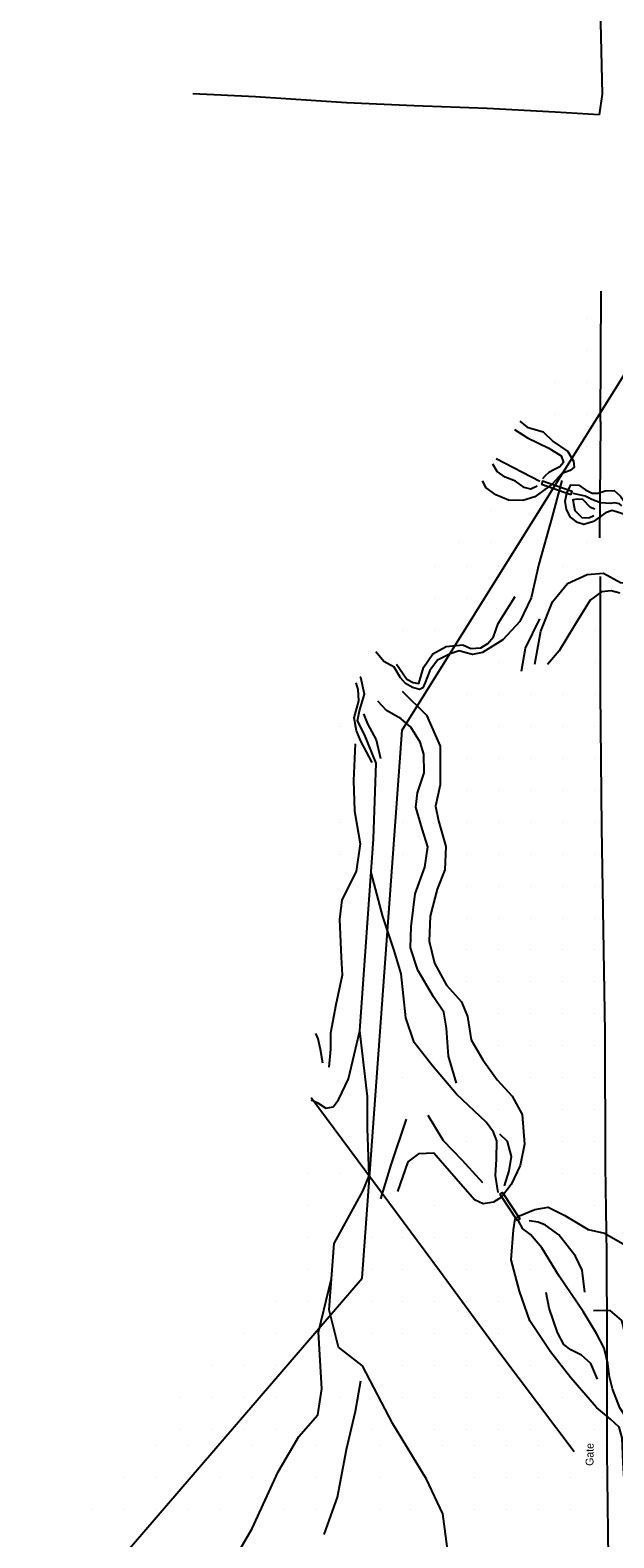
# Model space of a CAD drawing. Extents: x 19528164 to 19545171, y 7585743 to 7602745.
# Drawn here: x 19541417 to 19541782, y 7597047 to 7597991 of the extents above; entities that cross this region are included whole.
import ezdxf

# ---------------------------------------------------------------- set-up
doc = ezdxf.new("R2010")
doc.units = 0
for name, color, linetype in [('PhoBreakLine', 7, 'Continuous'), ('PhoCulvert', 7, 'Continuous'), ('PhoDrainageArrow', 7, 'Continuous'), ('PhoFence', 7, 'Continuous'), ('PhoISAEPoints', 7, 'Continuous'), ('PhoNotesDesign', 7, 'Continuous'), ('PhoSurveyLimits', 7, 'Continuous'), ('SurBreakLine', 7, 'Continuous'), ('SurEdgeEntranceUnpaved', 7, 'Continuous')]:
    doc.layers.add(name, color=color, linetype=linetype)

msp = doc.modelspace()

# ---------------------------------------------------------------- linework, layer by layer
at = {"layer": 'PhoBreakLine'}
for points in [[(19541723.1, 7597745.86), (19541727.72, 7597742.14), (19541737.65, 7597739.17), (19541744.06, 7597733.16), (19541753.15, 7597726.84), (19541756.71, 7597720.88), (19541757.17, 7597717.01), (19541754.71, 7597714.93), (19541749.52, 7597713.12), (19541743.3, 7597706.43), (19541732.59, 7597698.53), (19541724.92, 7597696.19), (19541716.1, 7597696.55), (19541708.08, 7597699.87), (19541702.1, 7597704.14), (19541699.82, 7597708.59)], [(19541719.9, 7597740.74), (19541727.87, 7597735.55), (19541741.23, 7597729.07), (19541748.96, 7597724.11), (19541750.44, 7597720.12), (19541748.08, 7597717.24), (19541744.37, 7597715.44), (19541741.19, 7597713.71), (19541739.03, 7597711.63), (19541737.32, 7597709.82)], [(19541733.96, 7597705.23), (19541730.07, 7597703.39), (19541725.87, 7597704.4), (19541720.42, 7597708.37), (19541713.98, 7597710.82), (19541708.94, 7597714.39), (19541706.25, 7597718.89)], [(19541749.32, 7597708.66), (19541743.07, 7597685.46), (19541734.99, 7597656.4), (19541730.3, 7597635.35), (19541723.22, 7597620.51), (19541712.57, 7597608.96), (19541699.77, 7597601.11), (19541693.51, 7597599.91), (19541688.72, 7597601.08), (19541685.1, 7597602.23), (19541679.56, 7597600.28), (19541671.6, 7597596.34), (19541666.84, 7597589.94), (19541663.88, 7597582.29), (19541662.37, 7597579.1), (19541660.29, 7597578), (19541655.91, 7597579.32), (19541651.51, 7597581.84), (19541648.43, 7597585.27), (19541644.46, 7597592.02), (19541638.04, 7597595.49), (19541632.9, 7597601.51)], [(19541790.02, 7597687.08), (19541780.99, 7597689.93), (19541776.86, 7597688.62), (19541769.15, 7597683.21), (19541763.12, 7597681.25), (19541759.23, 7597682.58), (19541754.77, 7597685.81), (19541752.34, 7597690.71), (19541751.47, 7597695.78), (19541752.59, 7597700.91), (19541755.01, 7597706.11), (19541760, 7597705.74), (19541764.14, 7597703), (19541768.36, 7597700.74), (19541772.19, 7597700.8), (19541776.62, 7597702.38), (19541782.18, 7597702.46), (19541786.15, 7597698.87), (19541789.93, 7597693.58), (19541789.8, 7597690.06)], [(19541770.15, 7597690.88), (19541767.29, 7597691.78), (19541762.58, 7597696.96), (19541759.37, 7597697.05), (19541756.31, 7597696.69), (19541757.65, 7597690.08), (19541761.99, 7597685.6), (19541766.4, 7597685.31), (19541769.36, 7597686.91)], [(19541732.47, 7597593.93), (19541736.31, 7597614.51), (19541743.61, 7597632.88), (19541753.02, 7597644.28), (19541765.27, 7597649.93), (19541775.46, 7597650.8), (19541786.14, 7597644.85), (19541799.39, 7597643.17), (19541811.74, 7597638.99), (19541823.27, 7597630.34), (19541832.56, 7597627.85), (19541841.75, 7597627.23)], [(19541645.9, 7597593.78), (19541652.41, 7597584.39), (19541656.4, 7597582.36), (19541659.88, 7597581.69), (19541662.76, 7597591.84), (19541668.61, 7597600.3), (19541677.09, 7597604.83), (19541687.54, 7597605.97), (19541692.43, 7597603.54), (19541698.74, 7597604.04), (19541703.11, 7597606.73), (19541706.66, 7597610.92), (19541709.52, 7597619.33), (19541720.14, 7597636.27)], [(19541785.75, 7597638.25), (19541780.28, 7597639.67), (19541774.31, 7597639.15), (19541767.22, 7597633.82), (19541757.4, 7597618.05), (19541747.81, 7597602.11), (19541740.55, 7597593.55)], [(19541724.27, 7597589.51), (19541726.59, 7597603.93), (19541735.75, 7597622.3)], [(19541630.8, 7597532.29), (19541623.52, 7597545.63), (19541620.98, 7597552.18), (19541619.34, 7597560.31), (19541622.31, 7597570.82), (19541621.98, 7597577.89), (19541620.75, 7597582.07)], [(19541649.49, 7597576.87), (19541664.76, 7597561.95), (19541673.37, 7597542.44), (19541673.23, 7597518.3), (19541670.31, 7597504.94), (19541672.27, 7597495.8), (19541676.78, 7597479.66), (19541676.1, 7597465.22), (19541671.38, 7597453.04), (19541666.95, 7597436.05), (19541666.33, 7597420.41), (19541669.65, 7597406.75), (19541677.15, 7597392.96), (19541686.7, 7597382.64), (19541690.35, 7597373.43), (19541692.7, 7597358.77), (19541699.96, 7597346.36), (19541708.92, 7597333.71), (19541718.37, 7597323.52), (19541724.59, 7597312.08), (19541726.11, 7597293.4), (19541723.37, 7597280.04), (19541717.66, 7597268.2), (19541711.72, 7597260.37), (19541706.74, 7597257.14), (19541700.25, 7597256.24), (19541694.78, 7597258.61), (19541683.28, 7597271.84), (19541669.33, 7597287.76), (19541659.63, 7597287.49), (19541652.98, 7597282.36), (19541646.52, 7597263.92)], [(19541683.46, 7597331.61), (19541678.4, 7597348.59), (19541677.17, 7597366.16), (19541675.6, 7597375.98), (19541669.18, 7597385.63), (19541659.23, 7597402.28), (19541654.8, 7597416.28), (19541655.09, 7597429.65), (19541657.64, 7597450.12), (19541663.72, 7597466.87), (19541665.54, 7597479.45), (19541661.95, 7597490.75), (19541657.97, 7597504.36), (19541659.08, 7597513.38), (19541663.22, 7597525.9), (19541663.09, 7597537.52), (19541660.71, 7597545.06), (19541654.88, 7597554.46), (19541648.83, 7597559.71), (19541639.76, 7597564.84), (19541634.29, 7597570.59)], [(19541625.32, 7597562.85), (19541627.73, 7597556.51), (19541633.3, 7597546.57), (19541635.84, 7597534.77)], [(19541620.16, 7597544.02), (19541619.11, 7597521.1), (19541619.69, 7597502), (19541623.24, 7597481.34), (19541620.64, 7597464.12), (19541611.81, 7597446.31), (19541610.26, 7597434.04), (19541611.22, 7597410.41), (19541611.83, 7597399.29), (19541607.87, 7597380.71), (19541604.61, 7597362.98), (19541604.58, 7597353.01), (19541603.54, 7597341.77)], [(19541599.86, 7597344.08), (19541598.44, 7597352.78), (19541596.96, 7597359.44), (19541595.47, 7597362.68)], [(19541699.91, 7597269.24), (19541687.05, 7597283.57), (19541675.3, 7597295.64), (19541665.85, 7597311.44)], [(19541636.04, 7597259.27), (19541642.59, 7597280.56), (19541652.14, 7597309.11)], [(19541713.45, 7597267.34), (19541716.38, 7597276.88), (19541717.87, 7597285.79), (19541715.41, 7597295.16), (19541710.62, 7597299.65)], [(19541795.75, 7596912.33), (19541789.01, 7596945.85), (19541786.33, 7596982.08), (19541788.28, 7597023.7), (19541789.72, 7597063.68), (19541787.78, 7597094.06), (19541787.29, 7597109.81), (19541785.25, 7597116.43), (19541779.94, 7597121.37), (19541771.08, 7597128.81), (19541755.05, 7597147.28), (19541742.23, 7597163.64), (19541729.45, 7597183), (19541722.84, 7597201.43), (19541717.71, 7597221.16), (19541719.24, 7597239.84), (19541720.2, 7597246.68), (19541723.03, 7597248.61), (19541732.61, 7597252.67), (19541740.78, 7597254.06), (19541751.28, 7597248.94), (19541765.98, 7597240.04), (19541776.09, 7597237.72), (19541791.71, 7597228.84)], [(19541763.85, 7597200.84), (19541762.23, 7597214.58), (19541757.9, 7597223.32), (19541747.61, 7597236.85), (19541739.16, 7597242.79), (19541734.62, 7597244.67), (19541728.94, 7597245.47)], [(19541771.76, 7597146.39), (19541767.59, 7597156.19), (19541761.81, 7597161.42), (19541755.12, 7597164.78), (19541750.74, 7597168.12), (19541746.69, 7597175.54), (19541741.51, 7597190.82), (19541739.55, 7597200.57)], [(19541797.71, 7597110.7), (19541802.13, 7597125.51), (19541799.15, 7597140.88), (19541792.02, 7597162), (19541786.98, 7597183.11), (19541779.58, 7597189.35), (19541769.34, 7597189.29)], [(19541600.59, 7597049.3), (19541609.04, 7597072.62), (19541614.71, 7597102.33), (19541620.31, 7597126.34), (19541623.69, 7597145.3)]]:
    msp.add_lwpolyline(points, dxfattribs=at)
at = {"layer": 'PhoCulvert'}
for p, q in [((19541755.09, 7597699.74), (19541736.64, 7597706.21)), ((19541710.68, 7597262.25), (19541721.44, 7597245.73))]:
    msp.add_line(p, q, dxfattribs=at)
for points in [[(19541755.09, 7597699.74), (19541755.85, 7597701.92), (19541737.4, 7597708.39), (19541736.64, 7597706.21)], [(19541710.68, 7597262.25), (19541712.31, 7597263.31), (19541723.07, 7597246.79), (19541721.44, 7597245.73)]]:
    msp.add_lwpolyline(points, dxfattribs=at)
at = {"layer": 'PhoDrainageArrow'}
msp.add_line((19541735.69, 7597708.23), (19541708.38, 7597722.29), dxfattribs=at)
for points in [[(19541786.97, 7597692.87), (19541785.45, 7597694.17), (19541782.36, 7597694.7), (19541780.12, 7597694.27), (19541773.6, 7597694.7), (19541768.16, 7597696.82), (19541764.12, 7597699.05), (19541756.53, 7597700.66)], [(19541678.14, 7597038.63), (19541674.89, 7597062.11), (19541664.66, 7597083.83), (19541643.65, 7597118.47), (19541624.75, 7597154.78), (19541609.65, 7597166.56), (19541603.77, 7597189.89), (19541606.98, 7597231.3), (19541624.9, 7597263.99), (19541628.93, 7597273.62), (19541627.8, 7597303.41), (19541627.72, 7597323.36), (19541623.05, 7597364.33), (19541631.46, 7597484.45), (19541633.28, 7597531.8), (19541626.01, 7597549.86), (19541621.56, 7597558.46), (19541622.83, 7597564.55), (19541625.94, 7597575.08), (19541623.58, 7597585.48), (19541623.19, 7597585.96)], [(19541709.67, 7597263.17), (19541707.99, 7597273.84), (19541708.48, 7597284.08), (19541708.73, 7597295.67), (19541706.74, 7597301.03), (19541701.98, 7597307.25), (19541683.48, 7597324.8), (19541668.45, 7597342.58), (19541657.07, 7597357.15), (19541651.88, 7597372.44), (19541648.93, 7597400.02), (19541644.52, 7597414.6), (19541637.42, 7597435.85), (19541629.99, 7597463.4)], [(19541592.45, 7597321.29), (19541596.22, 7597319.54), (19541601.7, 7597316.02), (19541606.23, 7597316.85), (19541609.73, 7597321.23), (19541615.87, 7597334.39), (19541623.05, 7597364.33)], [(19541869.28, 7596982.98), (19541854.16, 7597003.81), (19541844.16, 7597016.82), (19541839.53, 7597029.11), (19541837.27, 7597044.4), (19541831.15, 7597053.31), (19541820.27, 7597065.93), (19541805.81, 7597091.14), (19541797.08, 7597101.96), (19541793.45, 7597109.51), (19541792.72, 7597116.12), (19541790.48, 7597121.1), (19541785.79, 7597128.46), (19541781.24, 7597140.49), (19541779.22, 7597147.88), (19541778.25, 7597156.19), (19541775.82, 7597165.87), (19541771.19, 7597174.93), (19541762.79, 7597188.82), (19541747.75, 7597210.8), (19541737, 7597228.64), (19541729.79, 7597237.06), (19541725.03, 7597240.56), (19541722.24, 7597245.49)], [(19541418.25, 7596875.86), (19541452.62, 7596909.19), (19541485.87, 7596946.26), (19541511.57, 7596977.54), (19541535.3, 7597018.21), (19541555.62, 7597053), (19541571.97, 7597088.43), (19541584.71, 7597110.46), (19541596.64, 7597124.12), (19541599.2, 7597140.35), (19541597.16, 7597175.77), (19541605.29, 7597209.5)]]:
    msp.add_lwpolyline(points, dxfattribs=at)
at = {"layer": 'PhoFence'}
for q in [(19541774.01, 7597827.32), (19541773.04, 7597672.87)]:
    msp.add_line((19541773.57, 7597745.59), q, dxfattribs=at)
for points in [[(19541777.72, 7597100.95), (19541777.8, 7597171.2), (19541777.66, 7597224.89), (19541776.78, 7597279.98), (19541776.55, 7597363.47), (19541774.39, 7597491.54), (19541773.67, 7597576.04), (19541773.63, 7597648.62)], [(19541757.22, 7597100.96), (19541711.25, 7597161.92), (19541672.75, 7597214.17), (19541645.99, 7597250.58), (19541592.54, 7597322.44)], [(19541781.43, 7596887.24), (19541779.78, 7596935.19), (19541778.75, 7597017.64), (19541777.72, 7597100.95)]]:
    msp.add_lwpolyline(points, dxfattribs=at)
at = {"layer": 'PhoISAEPoints'}
for p, q in [((19541765, 7597810), (19541765, 7597810)), ((19541765, 7597790), (19541765, 7597790)), ((19541745, 7597770), (19541745, 7597770)), ((19541765, 7597770), (19541765, 7597770)), ((19541745, 7597750), (19541745, 7597750)), ((19541765, 7597750), (19541765, 7597750)), ((19541765, 7597730), (19541765, 7597730)), ((19541705, 7597690), (19541705, 7597690)), ((19541685, 7597670), (19541685, 7597670)), ((19541705, 7597670), (19541705, 7597670)), ((19541725, 7597670), (19541725, 7597670)), ((19541765, 7597670), (19541765, 7597670)), ((19541670, 7597655), (19541670, 7597655)), ((19541690, 7597655), (19541690, 7597655)), ((19541710, 7597655), (19541710, 7597655)), ((19541750, 7597655), (19541750, 7597655)), ((19541670, 7597635), (19541670, 7597635)), ((19541690, 7597635), (19541690, 7597635)), ((19541650, 7597615), (19541650, 7597615)), ((19541670, 7597615), (19541670, 7597615)), ((19541770, 7597615), (19541770, 7597615)), ((19541710, 7597595), (19541710, 7597595)), ((19541770, 7597595), (19541770, 7597595)), ((19541690, 7597575), (19541690, 7597575)), ((19541710, 7597575), (19541710, 7597575)), ((19541730, 7597575), (19541730, 7597575)), ((19541750, 7597575), (19541750, 7597575)), ((19541770, 7597575), (19541770, 7597575)), ((19541610, 7597555), (19541610, 7597555)), ((19541690, 7597555), (19541690, 7597555)), ((19541710, 7597555), (19541710, 7597555)), ((19541730, 7597555), (19541730, 7597555)), ((19541750, 7597555), (19541750, 7597555)), ((19541770, 7597555), (19541770, 7597555)), ((19541650, 7597535), (19541650, 7597535)), ((19541690, 7597535), (19541690, 7597535)), ((19541710, 7597535), (19541710, 7597535)), ((19541730, 7597535), (19541730, 7597535)), ((19541750, 7597535), (19541750, 7597535)), ((19541770, 7597535), (19541770, 7597535)), ((19541690, 7597515), (19541690, 7597515)), ((19541710, 7597515), (19541710, 7597515)), ((19541730, 7597515), (19541730, 7597515)), ((19541750, 7597515), (19541750, 7597515)), ((19541770, 7597515), (19541770, 7597515)), ((19541610, 7597495), (19541610, 7597495)), ((19541650, 7597495), (19541650, 7597495)), ((19541690, 7597495), (19541690, 7597495)), ((19541710, 7597495), (19541710, 7597495)), ((19541730, 7597495), (19541730, 7597495)), ((19541750, 7597495), (19541750, 7597495)), ((19541770, 7597495), (19541770, 7597495)), ((19541610, 7597475), (19541610, 7597475)), ((19541650, 7597475), (19541650, 7597475)), ((19541690, 7597475), (19541690, 7597475)), ((19541710, 7597475), (19541710, 7597475)), ((19541730, 7597475), (19541730, 7597475)), ((19541750, 7597475), (19541750, 7597475)), ((19541770, 7597475), (19541770, 7597475)), ((19541690, 7597455), (19541690, 7597455)), ((19541710, 7597455), (19541710, 7597455)), ((19541730, 7597455), (19541730, 7597455)), ((19541750, 7597455), (19541750, 7597455)), ((19541770, 7597455), (19541770, 7597455)), ((19541690, 7597435), (19541690, 7597435)), ((19541710, 7597435), (19541710, 7597435)), ((19541730, 7597435), (19541730, 7597435)), ((19541750, 7597435), (19541750, 7597435)), ((19541770, 7597435), (19541770, 7597435)), ((19541690, 7597415), (19541690, 7597415)), ((19541710, 7597415), (19541710, 7597415)), ((19541730, 7597415), (19541730, 7597415)), ((19541750, 7597415), (19541750, 7597415)), ((19541770, 7597415), (19541770, 7597415)), ((19541690, 7597395), (19541690, 7597395)), ((19541710, 7597395), (19541710, 7597395)), ((19541730, 7597395), (19541730, 7597395)), ((19541750, 7597395), (19541750, 7597395)), ((19541770, 7597395), (19541770, 7597395)), ((19541710, 7597375), (19541710, 7597375)), ((19541730, 7597375), (19541730, 7597375)), ((19541750, 7597375), (19541750, 7597375)), ((19541770, 7597375), (19541770, 7597375)), ((19541710, 7597355), (19541710, 7597355)), ((19541730, 7597355), (19541730, 7597355)), ((19541750, 7597355), (19541750, 7597355)), ((19541770, 7597355), (19541770, 7597355)), ((19541650, 7597335), (19541650, 7597335)), ((19541730, 7597335), (19541730, 7597335)), ((19541750, 7597335), (19541750, 7597335)), ((19541770, 7597335), (19541770, 7597335)), ((19541710, 7597315), (19541710, 7597315)), ((19541750, 7597315), (19541750, 7597315)), ((19541770, 7597315), (19541770, 7597315)), ((19541610, 7597295), (19541610, 7597295)), ((19541690, 7597295), (19541690, 7597295)), ((19541750, 7597295), (19541750, 7597295)), ((19541770, 7597295), (19541770, 7597295)), ((19541590, 7597275), (19541590, 7597275)), ((19541610, 7597275), (19541610, 7597275)), ((19541750, 7597275), (19541750, 7597275)), ((19541770, 7597275), (19541770, 7597275)), ((19541590, 7597255), (19541590, 7597255)), ((19541670, 7597255), (19541670, 7597255)), ((19541770, 7597255), (19541770, 7597255)), ((19541590, 7597235), (19541590, 7597235)), ((19541630, 7597235), (19541630, 7597235)), ((19541650, 7597235), (19541650, 7597235)), ((19541670, 7597235), (19541670, 7597235)), ((19541690, 7597235), (19541690, 7597235)), ((19541590, 7597215), (19541590, 7597215)), ((19541630, 7597215), (19541630, 7597215)), ((19541650, 7597215), (19541650, 7597215)), ((19541670, 7597215), (19541670, 7597215)), ((19541690, 7597215), (19541690, 7597215)), ((19541730, 7597215), (19541730, 7597215)), ((19541570, 7597195), (19541570, 7597195)), ((19541590, 7597195), (19541590, 7597195)), ((19541630, 7597195), (19541630, 7597195)), ((19541650, 7597195), (19541650, 7597195)), ((19541670, 7597195), (19541670, 7597195)), ((19541690, 7597195), (19541690, 7597195)), ((19541710, 7597195), (19541710, 7597195)), ((19541550, 7597175), (19541550, 7597175)), ((19541570, 7597175), (19541570, 7597175)), ((19541630, 7597175), (19541630, 7597175)), ((19541650, 7597175), (19541650, 7597175)), ((19541670, 7597175), (19541670, 7597175)), ((19541690, 7597175), (19541690, 7597175)), ((19541710, 7597175), (19541710, 7597175)), ((19541530, 7597155), (19541530, 7597155)), ((19541550, 7597155), (19541550, 7597155)), ((19541570, 7597155), (19541570, 7597155)), ((19541650, 7597155), (19541650, 7597155)), ((19541670, 7597155), (19541670, 7597155)), ((19541690, 7597155), (19541690, 7597155)), ((19541710, 7597155), (19541710, 7597155)), ((19541730, 7597155), (19541730, 7597155)), ((19541510, 7597135), (19541510, 7597135)), ((19541530, 7597135), (19541530, 7597135)), ((19541550, 7597135), (19541550, 7597135)), ((19541570, 7597135), (19541570, 7597135)), ((19541610, 7597135), (19541610, 7597135)), ((19541650, 7597135), (19541650, 7597135)), ((19541670, 7597135), (19541670, 7597135)), ((19541690, 7597135), (19541690, 7597135)), ((19541710, 7597135), (19541710, 7597135)), ((19541730, 7597135), (19541730, 7597135)), ((19541750, 7597135), (19541750, 7597135)), ((19541510, 7597115), (19541510, 7597115)), ((19541530, 7597115), (19541530, 7597115)), ((19541550, 7597115), (19541550, 7597115)), ((19541570, 7597115), (19541570, 7597115)), ((19541630, 7597115), (19541630, 7597115)), ((19541670, 7597115), (19541670, 7597115)), ((19541690, 7597115), (19541690, 7597115)), ((19541710, 7597115), (19541710, 7597115)), ((19541730, 7597115), (19541730, 7597115)), ((19541750, 7597115), (19541750, 7597115)), ((19541770, 7597115), (19541770, 7597115)), ((19541495, 7597105), (19541495, 7597105)), ((19541515, 7597105), (19541515, 7597105)), ((19541535, 7597105), (19541535, 7597105)), ((19541555, 7597105), (19541555, 7597105)), ((19541595, 7597105), (19541595, 7597105)), ((19541635, 7597105), (19541635, 7597105)), ((19541675, 7597105), (19541675, 7597105)), ((19541695, 7597105), (19541695, 7597105)), ((19541715, 7597105), (19541715, 7597105)), ((19541735, 7597105), (19541735, 7597105)), ((19541755, 7597105), (19541755, 7597105)), ((19541775, 7597105), (19541775, 7597105)), ((19541475, 7597085), (19541475, 7597085)), ((19541495, 7597085), (19541495, 7597085)), ((19541515, 7597085), (19541515, 7597085)), ((19541535, 7597085), (19541535, 7597085)), ((19541555, 7597085), (19541555, 7597085)), ((19541595, 7597085), (19541595, 7597085)), ((19541635, 7597085), (19541635, 7597085)), ((19541695, 7597085), (19541695, 7597085)), ((19541715, 7597085), (19541715, 7597085)), ((19541735, 7597085), (19541735, 7597085)), ((19541755, 7597085), (19541755, 7597085)), ((19541775, 7597085), (19541775, 7597085)), ((19541455, 7597065), (19541455, 7597065)), ((19541475, 7597065), (19541475, 7597065)), ((19541495, 7597065), (19541495, 7597065)), ((19541515, 7597065), (19541515, 7597065)), ((19541535, 7597065), (19541535, 7597065)), ((19541575, 7597065), (19541575, 7597065)), ((19541595, 7597065), (19541595, 7597065)), ((19541635, 7597065), (19541635, 7597065)), ((19541655, 7597065), (19541655, 7597065)), ((19541695, 7597065), (19541695, 7597065)), ((19541715, 7597065), (19541715, 7597065)), ((19541735, 7597065), (19541735, 7597065)), ((19541755, 7597065), (19541755, 7597065)), ((19541775, 7597065), (19541775, 7597065))]:
    msp.add_line(p, q, dxfattribs=at)
at = {"layer": 'PhoSurveyLimits'}
msp.add_lwpolyline([(19539053.39, 7595485.95), (19539048.98, 7595621.68), (19539215.71, 7595622.75), (19539469.49, 7595668.13), (19539712.52, 7595721.48), (19540033.03, 7595826.8), (19540393.26, 7595987.3), (19540770.63, 7595984.13), (19541136.8, 7596643.53), (19541624.4, 7597209.61), (19541649.44, 7597552.5), (19541832.46, 7597845.39), (19542376.97, 7598092.17)], dxfattribs=at)
at = {"layer": 'SurBreakLine'}
for points in [[(19541771.19, 7598364.43), (19541772.17, 7598276.88), (19541772.79, 7598209.4), (19541773.02, 7598139.24), (19541772.96, 7598084.64), (19541773.5, 7598004.27), (19541774.64, 7597950.56), (19541772.82, 7597937.47)], [(19541772.82, 7597937.47), (19541745.2, 7597939.27), (19541702.6, 7597941.48), (19541657.07, 7597943.3), (19541614.56, 7597945.08), (19541557.75, 7597948.83), (19541518.36, 7597950.73)]]:
    msp.add_lwpolyline(points, dxfattribs=at)
at = {"layer": 'SurEdgeEntranceUnpaved'}
msp.add_line((19541765, 7597810), (19541765, 7597810), dxfattribs=at)

# ---------------------------------------------------------------- texts
at = {"layer": 'PhoNotesDesign'}
msp.add_text('Gate', height=4.92, rotation=89.56168, dxfattribs=at).set_placement((19541769.22, 7597092.18))

doc.saveas('drawing.dxf')
